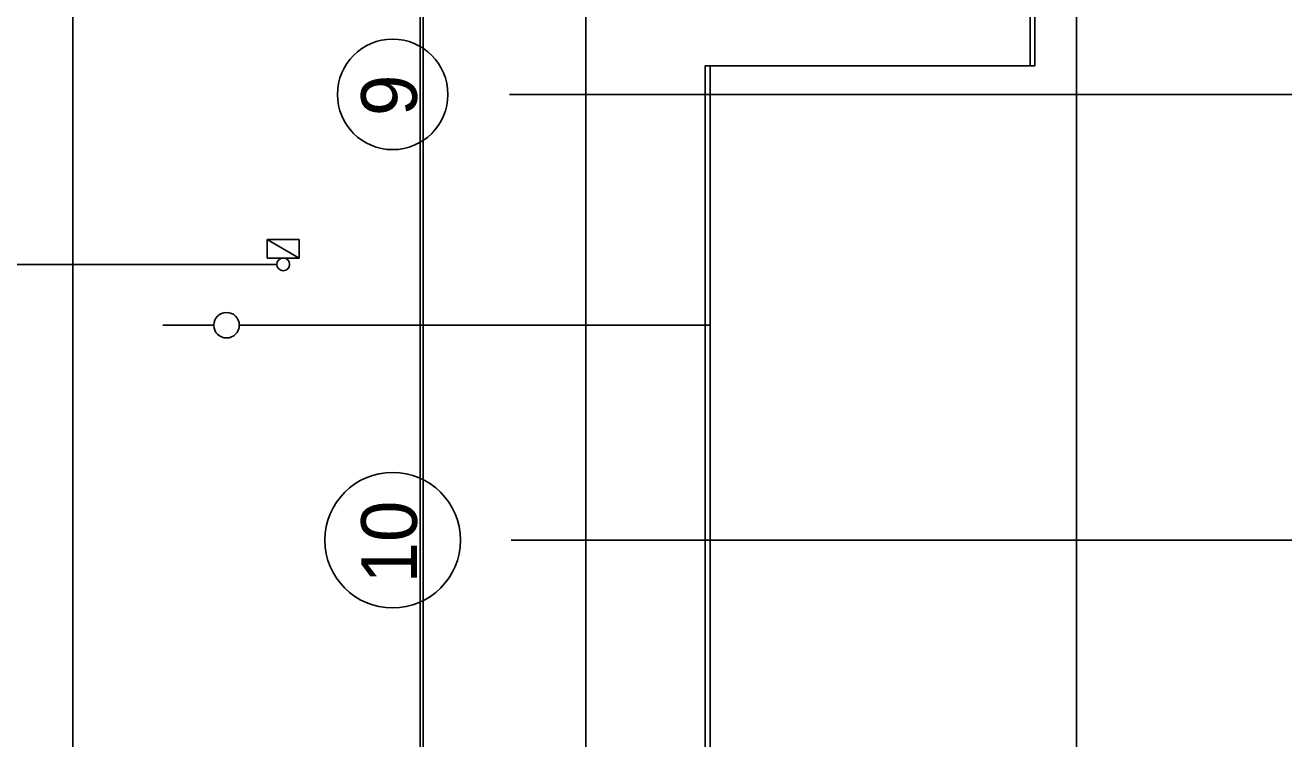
# Model space of a CAD drawing. Extents: x -264222 to -263592, y -1242345 to -1242048.
# Drawn here: x -263924.89 to -263905.14, y -1242143 to -1242131.8 of the extents above; entities that cross this region are included whole.
import ezdxf

# ---------------------------------------------------------------- set-up
doc = ezdxf.new("R2010")
doc.units = 0
for name, color, linetype in [('HESCON_OSI_STAVBY_KFA', 7, 'Continuous'), ('KFA_2D_SITUACIA_DSP', 7, 'Continuous'), ('KFA_SO_62-1_VO_TRASA_KABLOV_PROJEKT', 7, 'Continuous')]:
    doc.layers.add(name, color=color, linetype=linetype)

msp = doc.modelspace()

# ---------------------------------------------------------------- linework, layer by layer
at = {"layer": 'HESCON_OSI_STAVBY_KFA'}
for p, q in [((-263908.393, -1242083.237), (-263908.393, -1242246.707)), ((-263792.653, -1242132.882), (-263917.293, -1242132.882)), ((-263917.265, -1242139.882), (-263905.505, -1242139.882)), ((-263917.265, -1242139.882), (-263905.505, -1242139.882)), ((-263792.653, -1242139.882), (-263909.343, -1242139.882))]:
    msp.add_line(p, q, dxfattribs=at)
for centre, radius in [((-263919.125, -1242132.883), 0.867), ((-263919.125, -1242139.882), 1.064)]:
    msp.add_circle(centre, radius, dxfattribs=at)
at = {"layer": 'KFA_2D_SITUACIA_DSP'}
for p, q in [((-263924.143, -1242082.64), (-263924.143, -1242185.14)), ((-263909.118, -1242132.432), (-263909.118, -1242125.432)), ((-263914.218, -1242132.432), (-263909.118, -1242132.432)), ((-263914.218, -1242196.332), (-263914.218, -1242132.432)), ((-263921.093, -1242135.452), (-263921.093, -1242135.162)), ((-263921.093, -1242135.162), (-263920.593, -1242135.162)), ((-263920.593, -1242135.452), (-263921.093, -1242135.162)), ((-263920.593, -1242135.452), (-263921.093, -1242135.162)), ((-263921.093, -1242135.162), (-263921.093, -1242135.452)), ((-263920.593, -1242135.162), (-263920.593, -1242135.452)), ((-263920.593, -1242135.452), (-263921.093, -1242135.452)), ((-263921.093, -1242135.452), (-263920.593, -1242135.452)), ((-263920.943, -1242135.552), (-263925.797, -1242135.552)), ((-263921.932, -1242136.507), (-263922.732, -1242136.507)), ((-263917.093, -1242136.507), (-263921.532, -1242136.507)), ((-263917.093, -1242136.507), (-263914.143, -1242136.507))]:
    msp.add_line(p, q, dxfattribs=at)
msp.add_lwpolyline([(-263794.893, -1242227.382), (-263808.968, -1242241.457), (-263894.968, -1242241.457), (-263909.043, -1242227.382), (-263909.043, -1242196.333), (-263914.143, -1242196.333), (-263914.143, -1242132.433), (-263909.043, -1242132.433), (-263909.043, -1242101.382), (-263894.968, -1242087.307), (-263808.968, -1242087.307), (-263794.893, -1242101.382), (-263794.893, -1242227.382)], dxfattribs=at)
msp.add_lwpolyline([(-263893.618, -1242118.282), (-263916.093, -1242118.282), (-263916.093, -1242175.482), (-263914.293, -1242175.482), (-263914.293, -1242210.482), (-263893.618, -1242210.482), (-263893.618, -1242166.382), (-263900.043, -1242166.382), (-263900.043, -1242162.382), (-263893.618, -1242162.382)], close=True, dxfattribs=at)
for centre, radius in [((-263920.843, -1242135.552), 0.1), ((-263921.732, -1242136.507), 0.2)]:
    msp.add_circle(centre, radius, dxfattribs=at)
at = {"layer": 'KFA_SO_62-1_VO_TRASA_KABLOV_PROJEKT'}
for p, q in [((-263918.645, -1242194.9), (-263918.645, -1242084.831)), ((-263918.695, -1242110.308), (-263918.695, -1242194.95))]:
    msp.add_line(p, q, dxfattribs=at)

# ---------------------------------------------------------------- texts
at = {"layer": 'HESCON_OSI_STAVBY_KFA'}
for s, p in [('9', (-263918.744, -1242133.223)), ('10', (-263918.744, -1242140.562))]:
    msp.add_text(s, height=0.875, rotation=90, dxfattribs=at).set_placement(p)

doc.saveas('drawing.dxf')
